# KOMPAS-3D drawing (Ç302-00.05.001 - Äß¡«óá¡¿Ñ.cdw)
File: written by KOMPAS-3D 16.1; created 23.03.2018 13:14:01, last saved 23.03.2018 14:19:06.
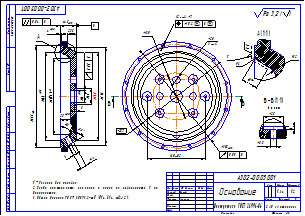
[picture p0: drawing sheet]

Sheet 1: A3, landscape

Title block, sheet 1: name: Основание; designation: А302-00.05.001; material: Полипропилен  ГОСТ 26996-86; mass: 1,34; scale: 1:2; sheets: 1; organisation: ЗАО «Астерион»; sheet format: A3; stored path: \\192.168.87.28\Konstructor_doc\Мембранные насосы\Мембранный электропривод\А302-00.00.000 - ASTRA-302 (МЭ200)\Чертежи\А302-00.05.001 - Основание.cdw; drawn by: Милов; technical control: Лучихин

Views: Вид 1, Местный разрез 1, Вид:3, Проекционный вид 2, Выносной элемент 3, Разрез Б-Б, Выносной элемент А, Выносной элемент
Referenced files in Z:\Мембранные насосы\Мембранный электропривод\А302-00.00.000 - ASTRA-302 (МЭ200)\3Д\: А302-00.05.001 - Основание.m3d
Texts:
  *Размеры для справок.
  Следы инструмента, царапины и риски на поверхности  Г  не
  допускаются.
  Общие допуски ГОСТ 30893.2-mK (H14, h14,  t2/2).
  Ra 3,2
  Ra 3,2 ( )
Dimensions and other numbers on the sheet: 16; 9; 45; 34; 4; 23,5; 44,5; 245; 272; 0,05; 28; 5; 280; 211,67; 244; 0,04; 302; 20; 3 отв.; 130; 160±0,2; 287; 12 отв.; 7; 6; 12; 2,5; 15; 6 мест; 8,5; 1:2; 1; 1,34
